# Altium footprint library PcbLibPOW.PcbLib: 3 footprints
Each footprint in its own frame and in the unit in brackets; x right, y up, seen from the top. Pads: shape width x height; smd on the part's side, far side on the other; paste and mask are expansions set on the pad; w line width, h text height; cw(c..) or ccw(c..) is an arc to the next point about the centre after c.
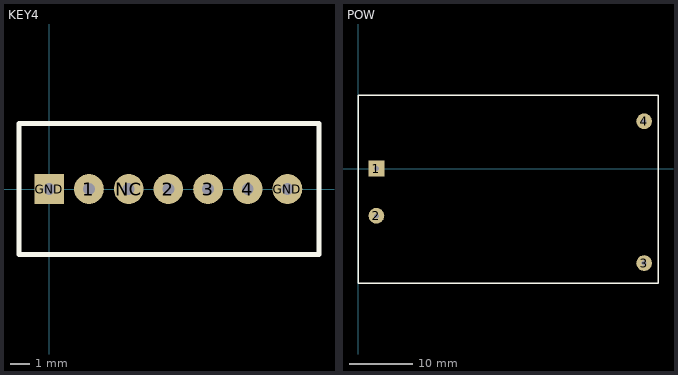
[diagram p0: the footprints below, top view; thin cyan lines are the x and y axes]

## KEY4 [mm]
pads (7):
  round 1.5 hole 0.6: 1(2,0) 2(6,0) 3(8,0) 4(10,0) GND(12,0) NC(4,0)
  rect 1.5x1.5 hole 0.6: GND(0,0)
Top Overlay:
  lines w0.254: -1.524,-3.302 -1.524,3.302 13.589,3.302 13.589,-3.302 -1.524,-3.302

## PCBComponent_1 [mm]

## POW [mm]
pads (4):
  rect 2.5x2.5 hole 0.8: 1(2.921,0)
  round 2.5 hole 0.8: 2(2.921,-7.5) 3(45.421,-15) 4(45.421,7.5)
Top Overlay:
  lines w0.2: 0,-18.161 47.625,-18.161 47.625,11.684 0,11.684 0,-18.161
